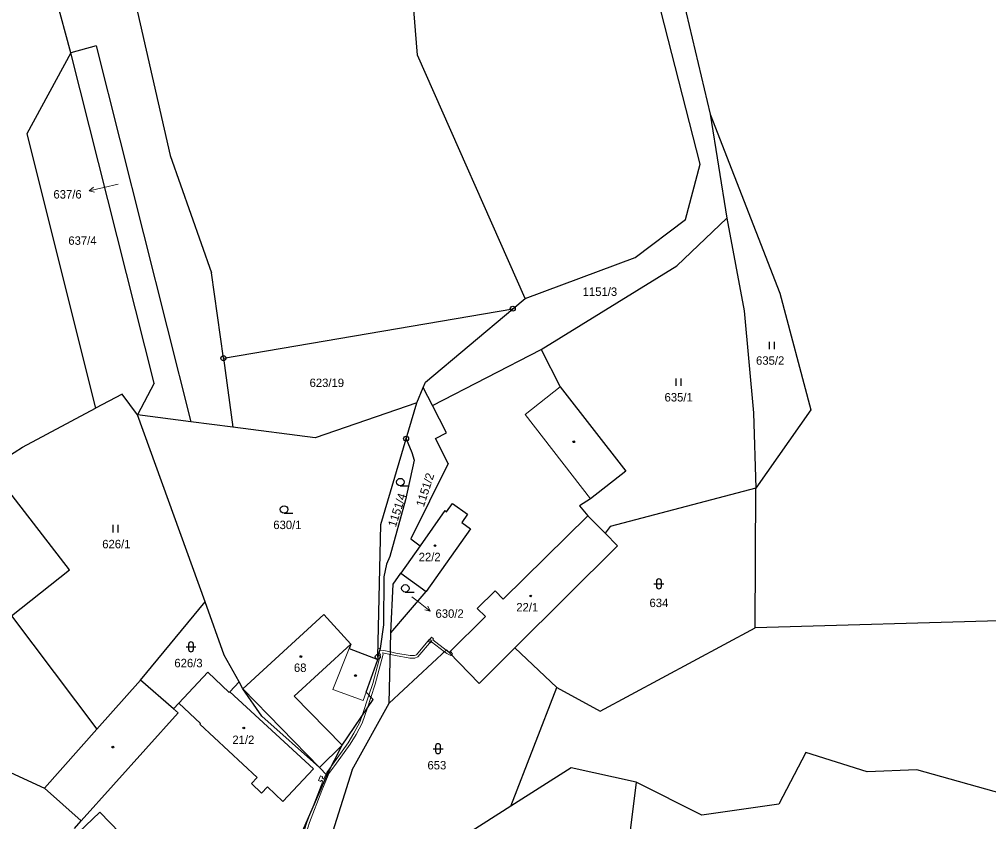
# Model space of a CAD drawing. Extents: x -765428 to -762163, y -1107632 to -1104975.
# Drawn here: x -764323.7 to -764128.3, y -1105896.5 to -1105734.6 of the extents above; entities that cross this region are included whole.
import ezdxf
from ezdxf.enums import TextEntityAlignment as Align

# ---------------------------------------------------------------- set-up
doc = ezdxf.new("R2010")
doc.units = 0
doc.header["$LTSCALE"] = 0.68
for name, color, linetype, lineweight in [('1', 7, 'Continuous', 25), ('13', 7, 'Continuous', 13), ('3', 7, 'Continuous', 25), ('4', 7, 'Continuous', 13), ('5', 7, 'Continuous', 25), ('7', 7, 'Continuous', 13), ('8', 7, 'Continuous', 25)]:
    doc.layers.add(name, color=color, linetype=linetype, lineweight=lineweight)
doc.layers.add('2', color=7, linetype='Continuous')

msp = doc.modelspace()

# ---------------------------------------------------------------- linework, layer by layer
at = {"layer": '1'}
for p, q in [((-764243.45, -1105741.86), (-764250.39, -1105655.59)), ((-764307.24, -1105700.64), (-764293.35, -1105762.11)), ((-764313.35, -1105741.37), (-764322.45, -1105708.04)), ((-764186.48, -1105763.83), (-764197.65, -1105720.28)), ((-764189.9, -1105730.69), (-764184.45, -1105753.78)), ((-764308.21, -1105740), (-764313.35, -1105741.37)), ((-764308.21, -1105740), (-764289.16, -1105815.79)), ((-764313.35, -1105741.37), (-764322.18, -1105757.71)), ((-764296.52, -1105808), (-764313.35, -1105741.37)), ((-764221.77, -1105790.92), (-764243.45, -1105741.86)), ((-764184.45, -1105753.78), (-764170.43, -1105789.87)), ((-764184.45, -1105753.78), (-764181.07, -1105774.74)), ((-764322.18, -1105757.71), (-764308.37, -1105813.05)), ((-764293.35, -1105762.11), (-764284.97, -1105785.79)), ((-764189.45, -1105774.99), (-764186.48, -1105763.83)), ((-764199.57, -1105782.71), (-764189.45, -1105774.99)), ((-764191.15, -1105784.33), (-764181.07, -1105774.74)), ((-764181.07, -1105774.74), (-764177.6, -1105793.42)), ((-764221.77, -1105790.92), (-764199.57, -1105782.71)), ((-764218.53, -1105801.26), (-764191.15, -1105784.33)), ((-764282.59, -1105802.98), (-764284.97, -1105785.79)), ((-764224.25, -1105793), (-764221.77, -1105790.92)), ((-764170.43, -1105789.87), (-764164.15, -1105813.42)), ((-764282.59, -1105802.98), (-764224.25, -1105793)), ((-764241.84, -1105807.81), (-764224.25, -1105793)), ((-764177.6, -1105793.42), (-764175.74, -1105813.99)), ((-764240.46, -1105812.51), (-764218.53, -1105801.26)), ((-764282.59, -1105802.98), (-764280.66, -1105816.88)), ((-764296.52, -1105808), (-764299.91, -1105814.41)), ((-764242.31, -1105808.91), (-764241.84, -1105807.81)), ((-764302.98, -1105810.23), (-764308.37, -1105813.05)), ((-764299.91, -1105814.41), (-764302.98, -1105810.23)), ((-764243.62, -1105811.96), (-764242.31, -1105808.91)), ((-764240.46, -1105812.51), (-764242.31, -1105808.91)), ((-764243.62, -1105811.96), (-764264.09, -1105819.02)), ((-764245.76, -1105819.22), (-764243.62, -1105811.96)), ((-764323.07, -1105820.91), (-764308.37, -1105813.05)), ((-764286.29, -1105852.13), (-764299.91, -1105814.41)), ((-764289.16, -1105815.79), (-764299.91, -1105814.41)), ((-764237.62, -1105818.04), (-764240.46, -1105812.51)), ((-764175.74, -1105813.99), (-764175.28, -1105829.23)), ((-764164.15, -1105813.42), (-764175.28, -1105829.23)), ((-764280.66, -1105816.88), (-764289.16, -1105815.79)), ((-764264.09, -1105819.02), (-764280.66, -1105816.88)), ((-764239.85, -1105819.18), (-764237.62, -1105818.04)), ((-764250.86, -1105836.5), (-764245.76, -1105819.22)), ((-764245.76, -1105819.22), (-764244.58, -1105822.03)), ((-764237.25, -1105824.25), (-764239.85, -1105819.18)), ((-764329.52, -1105825.06), (-764323.07, -1105820.91)), ((-764244.58, -1105822.03), (-764244.11, -1105823.55)), ((-764244.11, -1105823.55), (-764245.89, -1105831.53)), ((-764313.6, -1105845.64), (-764329.52, -1105825.06)), ((-764237.25, -1105824.25), (-764244.82, -1105839.45)), ((-764201.46, -1105825.8), (-764208.6, -1105831.34)), ((-764175.28, -1105829.23), (-764204.63, -1105836.92)), ((-764175.37, -1105857.37), (-764175.28, -1105829.23)), ((-764245.89, -1105831.53), (-764249.05, -1105842.95)), ((-764208.6, -1105831.34), (-764210.78, -1105832.76)), ((-764237.93, -1105833.72), (-764242.9, -1105840.8)), ((-764237.93, -1105833.72), (-764237.61, -1105833.95)), ((-764237.61, -1105833.95), (-764236.42, -1105832.26)), ((-764236.42, -1105832.26), (-764233.35, -1105834.42)), ((-764210.78, -1105832.76), (-764209.13, -1105834.77)), ((-764233.35, -1105834.42), (-764234.54, -1105836.11)), ((-764205.64, -1105838.3), (-764209.13, -1105834.77)), ((-764251.47, -1105863.23), (-764250.86, -1105836.5)), ((-764232.76, -1105837.37), (-764241.69, -1105850.02)), ((-764234.54, -1105836.11), (-764232.76, -1105837.37)), ((-764204.63, -1105836.92), (-764205.64, -1105838.3)), ((-764244.82, -1105839.45), (-764242.9, -1105840.8)), ((-764203.13, -1105840.84), (-764205.64, -1105838.3)), ((-764242.9, -1105840.8), (-764246.8, -1105846.37)), ((-764223.83, -1105861.42), (-764203.13, -1105840.84)), ((-764249.05, -1105842.95), (-764249.72, -1105844.53)), ((-764325.31, -1105854.95), (-764313.6, -1105845.64)), ((-764249.72, -1105844.53), (-764250.26, -1105847.08)), ((-764250.26, -1105847.08), (-764250.3, -1105856.74)), ((-764248.35, -1105848.58), (-764246.8, -1105846.37)), ((-764246.8, -1105846.37), (-764241.69, -1105850.02)), ((-764248.82, -1105858.4), (-764248.35, -1105848.58)), ((-764248.82, -1105858.4), (-764241.69, -1105850.02)), ((-764299.27, -1105867.9), (-764286.29, -1105852.13)), ((-764278.7, -1105869.65), (-764262.37, -1105854.65)), ((-764256.87, -1105860.64), (-764262.37, -1105854.65)), ((-764097.45, -1105855.1), (-764175.37, -1105857.37)), ((-764250.3, -1105856.74), (-764251.01, -1105861.56)), ((-764206.61, -1105874.17), (-764175.37, -1105857.37)), ((-764249.19, -1105872.54), (-764248.82, -1105858.4)), ((-764256.87, -1105860.64), (-764257.23, -1105861.51)), ((-764257.23, -1105861.51), (-764251.48, -1105863.75)), ((-764251.47, -1105863.23), (-764251.48, -1105863.75)), ((-764251.01, -1105861.56), (-764251.47, -1105863.23)), ((-764249.19, -1105872.54), (-764237.62, -1105861.78)), ((-764237.08, -1105862.34), (-764237.62, -1105861.78)), ((-764237.08, -1105862.34), (-764231.04, -1105868.59)), ((-764231.04, -1105868.59), (-764223.83, -1105861.42)), ((-764215.35, -1105869.4), (-764223.83, -1105861.42)), ((-764253.83, -1105870.37), (-764251.48, -1105863.75)), ((-764291.57, -1105872.58), (-764285.72, -1105866.28)), ((-764285.72, -1105866.28), (-764281.43, -1105870.42)), ((-764299.27, -1105867.9), (-764308.1, -1105877.84)), ((-764292.62, -1105873.71), (-764299.27, -1105867.9)), ((-764279.44, -1105868.29), (-764281.29, -1105870.3)), ((-764278.7, -1105869.65), (-764279.44, -1105868.29)), ((-764281.43, -1105870.42), (-764281.29, -1105870.3)), ((-764274.82, -1105875.19), (-764278.7, -1105869.65)), ((-764252.42, -1105871.82), (-764253.83, -1105870.37)), ((-764224.62, -1105893.32), (-764215.35, -1105869.4)), ((-764215.35, -1105869.4), (-764206.61, -1105874.17)), ((-764292.62, -1105873.71), (-764291.57, -1105872.58)), ((-764258.63, -1105881.01), (-764252.42, -1105871.82)), ((-764256.61, -1105885.99), (-764249.19, -1105872.54)), ((-764350.48, -1105874.96), (-764318.67, -1105889.74)), ((-764263.24, -1105885.56), (-764274.82, -1105875.19)), ((-764261.77, -1105887.07), (-764258.63, -1105881.01)), ((-764165.15, -1105882.49), (-764170.61, -1105892.91)), ((-764152.84, -1105886.4), (-764165.15, -1105882.49)), ((-764263.24, -1105885.56), (-764261.77, -1105887.07)), ((-764256.61, -1105885.99), (-764261.45, -1105901.31)), ((-764212.47, -1105885.58), (-764224.62, -1105893.32)), ((-764199.41, -1105888.5), (-764212.47, -1105885.58)), ((-764142.78, -1105885.98), (-764152.84, -1105886.4)), ((-764117.43, -1105893.18), (-764142.78, -1105885.98)), ((-764261.77, -1105887.07), (-764266.65, -1105898.32)), ((-764199.41, -1105888.5), (-764201.24, -1105903.77)), ((-764186.15, -1105895.15), (-764199.41, -1105888.5)), ((-764318.67, -1105889.74), (-764311.27, -1105896.32)), ((-764224.62, -1105893.32), (-764249.1, -1105908.9)), ((-764170.61, -1105892.91), (-764186.15, -1105895.15)), ((-764312.61, -1105897.81), (-764311.27, -1105896.32))]:
    msp.add_line(p, q, dxfattribs=at)
for points in [[(-764218.53, -1105801.26), (-764214.67, -1105808.78), (-764201.46, -1105825.8)], [(-764279.44, -1105868.29), (-764282.4, -1105862.89), (-764286.29, -1105852.13)], [(-764325.31, -1105854.95), (-764308.1, -1105877.84), (-764318.67, -1105889.74)]]:
    msp.add_lwpolyline(points, dxfattribs=at)
at = {"layer": '13'}
for points in [[(-764236.98, -1105862.45), (-764237.08, -1105862.34), (-764237.7, -1105861.85), (-764240.36, -1105859.77), (-764240.21, -1105859.57), (-764240.62, -1105859.27), (-764241.21, -1105860.08), (-764240.81, -1105860.37), (-764240.66, -1105860.17), (-764238.05, -1105862.18), (-764237.57, -1105862.55), (-764236.77, -1105862.94), (-764236.42, -1105862.6), (-764236.76, -1105862.24)], [(-764243.38, -1105863.23), (-764240.63, -1105860.01), (-764241.01, -1105859.68), (-764243.68, -1105862.81), (-764244.09, -1105862.96), (-764244.97, -1105862.98), (-764247.81, -1105862.46), (-764248.92, -1105862.22), (-764248.93, -1105862.73), (-764247.91, -1105862.96), (-764245.01, -1105863.48), (-764243.99, -1105863.46)], [(-764252.84, -1105871.39), (-764251.97, -1105868.72), (-764250.4, -1105862.71), (-764250.49, -1105862.38), (-764248.93, -1105862.73), (-764248.92, -1105862.22), (-764250.22, -1105861.93), (-764250.96, -1105861.85), (-764250.93, -1105861.57), (-764251.43, -1105861.5), (-764251.45, -1105862.52), (-764250.96, -1105862.58), (-764250.9, -1105862.78), (-764252.45, -1105868.58), (-764253.24, -1105870.98)], [(-764252.84, -1105871.39), (-764253.24, -1105870.98), (-764254.61, -1105875.07), (-764253.55, -1105873.49)], [(-764265.9, -1105898.75), (-764265.22, -1105896.61), (-764262.74, -1105890.21), (-764262.07, -1105888.57), (-764261.3, -1105886.76), (-764259.77, -1105884.69), (-764257.02, -1105880.81), (-764255.84, -1105878.87), (-764254.61, -1105876.61), (-764253.55, -1105873.49), (-764254.61, -1105875.07), (-764255.07, -1105876.41), (-764256.28, -1105878.63), (-764257.44, -1105880.53), (-764260.17, -1105884.39), (-764260.88, -1105885.35), (-764261.77, -1105887.07), (-764264.48, -1105893.32), (-764265.7, -1105896.45), (-764266.34, -1105898.5)], [(-764261.74, -1105886.52), (-764261.91, -1105886.92), (-764261.77, -1105887.07), (-764260.88, -1105885.35)], [(-764263.43, -1105888.14), (-764262.97, -1105888.34), (-764262.87, -1105888.11), (-764262.51, -1105888.32), (-764263.2, -1105890.03), (-764264.48, -1105893.32), (-764261.77, -1105887.07), (-764261.91, -1105886.92), (-764262.31, -1105887.86), (-764262.67, -1105887.65), (-764262.57, -1105887.42), (-764263.03, -1105887.22)]]:
    msp.add_lwpolyline(points, close=True, dxfattribs=at)
at = {"layer": '3'}
for p, q in [((-764172.511, -1105801.18), (-764172.511, -1105799.68)), ((-764171.51, -1105801.18), (-764171.51, -1105799.68)), ((-764191.331, -1105808.59), (-764191.331, -1105807.09)), ((-764190.33, -1105808.59), (-764190.33, -1105807.09)), ((-764246.923, -1105828.72), (-764245.173, -1105828.72)), ((-764270.363, -1105834.24), (-764268.613, -1105834.24)), ((-764304.791, -1105838.11), (-764304.791, -1105836.61)), ((-764303.79, -1105838.11), (-764303.79, -1105836.61)), ((-764195.791, -1105848.501), (-764193.789, -1105848.501)), ((-764195.291, -1105848.001), (-764195.291, -1105849.002)), ((-764194.289, -1105849.002), (-764194.289, -1105848.001)), ((-764245.913, -1105850.16), (-764244.163, -1105850.16)), ((-764290.121, -1105861.201), (-764288.119, -1105861.201)), ((-764289.621, -1105860.701), (-764289.621, -1105861.702)), ((-764288.619, -1105861.702), (-764288.619, -1105860.701)), ((-764240.311, -1105881.741), (-764238.309, -1105881.741)), ((-764239.811, -1105881.241), (-764239.811, -1105882.242)), ((-764238.809, -1105882.242), (-764238.809, -1105881.241))]:
    msp.add_line(p, q, dxfattribs=at)
for centre in [(-764246.9229, -1105827.9698), (-764270.3629, -1105833.4898), (-764245.9129, -1105849.4098)]:
    msp.add_circle(centre, 0.75, dxfattribs=at)
for centre, start, end in [((-764194.79, -1105848.0009), 0, 180), ((-764194.79, -1105849.0009), 180, 359.98789), ((-764289.12, -1105860.7009), 0, 180), ((-764289.12, -1105861.7009), 180, 359.98789), ((-764239.31, -1105881.2409), 0, 180), ((-764239.31, -1105882.2409), 180, 359.98789)]:
    msp.add_arc(centre, 0.5, start, end, dxfattribs=at)
at = {"layer": '4'}
for p, q in [((-764214.67, -1105808.78), (-764221.78, -1105814.36)), ((-764208.6, -1105831.34), (-764221.78, -1105814.36)), ((-764226.17, -1105851.58), (-764209.13, -1105834.77)), ((-764231.42, -1105853.48), (-764227.77, -1105849.88)), ((-764227.77, -1105849.88), (-764226.17, -1105851.58)), ((-764229.75, -1105855.11), (-764231.42, -1105853.48)), ((-764237.08, -1105862.34), (-764229.75, -1105855.11)), ((-764256.87, -1105860.64), (-764268.34, -1105871.17)), ((-764257.23, -1105861.51), (-764260.56, -1105869.84)), ((-764281.29, -1105870.3), (-764264.44, -1105885.79)), ((-764263.24, -1105885.56), (-764278.7, -1105869.65)), ((-764254.41, -1105872.02), (-764260.56, -1105869.84)), ((-764253.83, -1105870.37), (-764254.41, -1105872.02)), ((-764287.21, -1105876.64), (-764291.57, -1105872.58)), ((-764268.34, -1105871.17), (-764258.63, -1105881.01)), ((-764311.27, -1105896.32), (-764291.71, -1105874.51)), ((-764291.71, -1105874.51), (-764292.62, -1105873.71)), ((-764287.33, -1105876.77), (-764287.21, -1105876.64)), ((-764275.76, -1105887.55), (-764287.33, -1105876.77)), ((-764258.63, -1105881.01), (-764263.24, -1105885.56)), ((-764264.44, -1105885.79), (-764270.58, -1105892.38)), ((-764276.9, -1105888.78), (-764275.76, -1105887.55)), ((-764274.89, -1105890.69), (-764276.9, -1105888.78)), ((-764273.73, -1105889.45), (-764274.89, -1105890.69)), ((-764270.58, -1105892.38), (-764273.73, -1105889.45)), ((-764307.52, -1105894.57), (-764311.77, -1105898.67)), ((-764307.52, -1105894.57), (-764297.1, -1105905.22))]:
    msp.add_line(p, q, dxfattribs=at)
at = {"layer": '5'}
for centre in [(-764211.9668, -1105819.8392), (-764239.9368, -1105840.7892), (-764220.6368, -1105850.9392), (-764266.9568, -1105863.1592), (-764255.9568, -1105866.9992), (-764278.4868, -1105877.5692), (-764304.8668, -1105881.4192)]:
    msp.add_circle(centre, 0.175, dxfattribs=at)
at = {"layer": '7'}
for p, q in [((-764309.644, -1105769.205), (-764308.556, -1105769.468)), ((-764240.915, -1105853.978), (-764241.396, -1105852.966))]:
    msp.add_line(p, q, dxfattribs=at)
for points in [[(-764303.83, -1105767.86), (-764306.72, -1105768.53), (-764309.644, -1105769.205), (-764308.781, -1105768.492)], [(-764244.63, -1105851.09), (-764243.28, -1105852.13), (-764240.915, -1105853.978), (-764242.013, -1105853.756)]]:
    msp.add_lwpolyline(points, dxfattribs=at)
at = {"layer": '8'}
for centre, radius in [((-764224.25, -1105792.9999), 0.5), ((-764224.25, -1105792.9999), 0.0303), ((-764282.59, -1105802.9799), 0.5), ((-764282.59, -1105802.9799), 0.0303), ((-764245.76, -1105819.2199), 0.5), ((-764245.76, -1105819.2199), 0.0303), ((-764251.47, -1105863.2299), 0.5), ((-764251.47, -1105863.2299), 0.0303)]:
    msp.add_circle(centre, radius, dxfattribs=at)

# ---------------------------------------------------------------- texts
at = {"layer": '2'}
msp.add_text('637/6', height=1.7, dxfattribs=at).set_placement((-764311.16, -1105770.785), align=Align.RIGHT)
for s, p in [('637/4', (-764311, -1105780.115)), ('1151/3', (-764206.69, -1105790.425)), ('623/19', (-764261.74, -1105808.805))]:
    msp.add_text(s, height=1.7, dxfattribs=at).set_placement(p, align=Align.CENTER)
for s, p in [('635/2', (-764175.21, -1105804.305)), ('635/1', (-764193.66, -1105811.715)), ('630/1', (-764272.53, -1105837.455)), ('626/1', (-764307.01, -1105841.325)), ('22/2', (-764243.22, -1105843.925)), ('634', (-764196.69, -1105853.185)), ('22/1', (-764223.54, -1105854.065)), ('630/2', (-764239.83, -1105855.345)), ('626/3', (-764292.47, -1105865.325)), ('68', (-764268.37, -1105866.265)), ('21/2', (-764280.78, -1105880.805)), ('653', (-764241.45, -1105885.925))]:
    msp.add_text(s, height=1.7, dxfattribs=at).set_placement(p)
for s, p in [('1151/2', (-764241.1214, -1105829.7977)), ('1151/4', (-764246.7714, -1105833.8777))]:
    msp.add_text(s, height=1.7, rotation=72, dxfattribs=at).set_placement(p, align=Align.CENTER)

doc.saveas('drawing.dxf')
